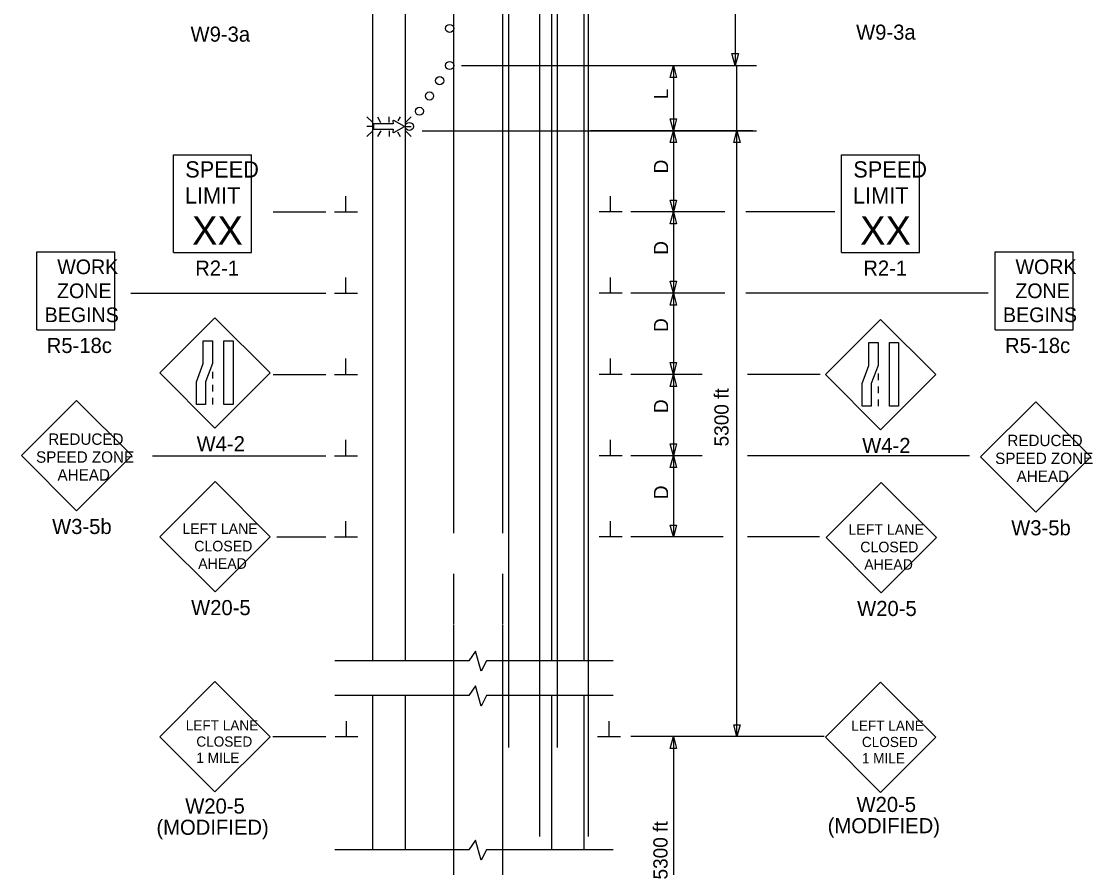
# Model space of a CAD drawing. Extents: x 16741 to 18482, y 7002 to 8333.
# Drawn here: x 16741 to 17268, y 7456 to 7872 of the extents above; entities that cross this region are included whole.
import ezdxf

# ---------------------------------------------------------------- set-up
doc = ezdxf.new("R2010")
doc.units = 0
for name, color, linetype in [('ALI_LEGAL_EX', 7, 'Continuous'), ('PAVT_EDGE_EX', 7, 'Continuous'), ('TRAFFIC_SIGNS_PR', 7, 'Continuous'), ('TYPICAL_TEXT_DIMEN_PR', 7, 'Continuous')]:
    doc.layers.add(name, color=color, linetype=linetype)

msp = doc.modelspace()

# ---------------------------------------------------------------- linework, layer by layer
at = {"layer": 'ALI_LEGAL_EX'}
for p, q in [((16980.68, 8333.08), (16980.68, 7514.94)), ((17004.68, 8333.08), (17004.68, 7514.94)), ((16995.95, 8289.26), (16995.95, 7471.12)), ((17019.95, 8289.26), (17019.95, 7471.12)), ((16953.87, 7620.35), (16953.87, 8241.48)), ((16977.87, 7620.35), (16977.87, 8241.48)), ((16953.87, 7497.94), (16953.87, 7575.09)), ((16977.87, 7497.94), (16977.87, 7575.09)), ((16953.87, 7379.99), (16953.87, 7560.8)), ((16977.87, 7379.99), (16977.87, 7560.8))]:
    msp.add_line(p, q, dxfattribs=at)
for points in [[(16953.87, 7775.35), (16953.87, 7800.35)], [(16977.87, 7775.35), (16977.87, 7800.35)], [(16953.87, 7675.35), (16953.87, 7700.35)], [(16977.87, 7675.35), (16977.87, 7700.35)], [(16953.87, 7575.35), (16953.87, 7600.35)], [(16977.87, 7575.35), (16977.87, 7600.35)], [(16953.87, 7475.35), (16953.87, 7500.35)], [(16977.87, 7475.35), (16977.87, 7500.35)]]:
    msp.add_lwpolyline(points, dxfattribs=at)
at = {"layer": 'PAVT_EDGE_EX'}
for p, q in [((16913.87, 8212.75), (16913.87, 7557.55)), ((16929.87, 8212.75), (16929.87, 7557.55)), ((17001.87, 8212.75), (17001.87, 7557.55)), ((17017.87, 8212.75), (17017.87, 7557.55)), ((16913.87, 7540.42), (16913.87, 7464.49)), ((16929.87, 7540.42), (16929.87, 7464.49)), ((17001.87, 7540.42), (17001.87, 7464.49)), ((17017.87, 7540.42), (17017.87, 7464.49))]:
    msp.add_line(p, q, dxfattribs=at)
at = {"layer": 'TRAFFIC_SIGNS_PR'}
for p, q in [((16913.89, 7822.57), (16911.06, 7825.39)), ((16916.18, 7825.39), (16917.81, 7822.57)), ((16921.97, 7822.57), (16921.97, 7825.39)), ((16927.44, 7825.39), (16926.23, 7823.3)), ((16932.87, 7825.39), (16930.06, 7822.57)), ((16913.89, 7820.54), (16911.06, 7820.54)), ((16930.06, 7820.54), (16932.87, 7820.54)), ((16913.89, 7818.5), (16911.06, 7815.68)), ((16917.83, 7818.5), (16916.21, 7815.68)), ((16921.97, 7818.5), (16921.97, 7815.68)), ((16926.15, 7817.87), (16927.41, 7815.68)), ((16932.87, 7815.69), (16930.06, 7818.5)), ((16815.84, 7806.57), (16854.24, 7806.57)), ((16815.84, 7758.57), (16815.84, 7806.57)), ((16854.24, 7758.57), (16854.24, 7806.57)), ((17144.69, 7806.57), (17183.09, 7806.57)), ((17144.69, 7758.57), (17144.69, 7806.57)), ((17183.09, 7758.57), (17183.09, 7806.57)), ((16748.63, 7720.5), (16748.63, 7758.9)), ((16748.63, 7758.9), (16787.03, 7758.9)), ((16787.03, 7720.5), (16787.03, 7758.9)), ((16815.84, 7758.57), (16854.24, 7758.57)), ((17144.69, 7758.57), (17183.09, 7758.57)), ((17220.32, 7720.5), (17220.32, 7758.9)), ((17220.32, 7758.9), (17258.72, 7758.9)), ((17258.72, 7720.5), (17258.72, 7758.9)), ((16836.26, 7726.42), (16809.1, 7699.26)), ((16863.41, 7699.26), (16836.26, 7726.42)), ((17163.88, 7725.58), (17136.72, 7698.43)), ((17191.03, 7698.43), (17163.88, 7725.58)), ((16748.63, 7720.5), (16787.03, 7720.5)), ((17220.32, 7720.5), (17258.72, 7720.5)), ((16809.1, 7699.26), (16836.26, 7672.11)), ((16835.01, 7699.75), (16835.01, 7696.55)), ((16836.26, 7672.11), (16863.41, 7699.26)), ((17136.72, 7698.43), (17163.88, 7671.27)), ((17162.63, 7698.92), (17162.63, 7695.72)), ((17163.88, 7671.27), (17191.03, 7698.43)), ((16835.01, 7693.35), (16835.01, 7690.15)), ((17162.63, 7692.52), (17162.63, 7689.32)), ((16768.14, 7685.7), (16740.98, 7658.54)), ((16795.29, 7658.54), (16768.14, 7685.7)), ((16835.01, 7686.95), (16835.01, 7683.75)), ((17162.63, 7686.12), (17162.63, 7682.92)), ((17240.23, 7685.06), (17213.08, 7657.9)), ((17267.38, 7657.9), (17240.23, 7685.06)), ((16740.98, 7658.54), (16768.14, 7631.39)), ((16768.14, 7631.39), (16795.29, 7658.54)), ((17213.08, 7657.9), (17240.23, 7630.75)), ((17240.23, 7630.75), (17267.38, 7657.9)), ((16836.33, 7645.76), (16809.18, 7618.6)), ((16863.48, 7618.6), (16836.33, 7645.76)), ((17164.17, 7645.32), (17137.02, 7618.17)), ((17191.33, 7618.17), (17164.17, 7645.32)), ((16809.18, 7618.6), (16836.33, 7591.45)), ((16836.33, 7591.45), (16863.48, 7618.6)), ((17137.02, 7618.17), (17164.17, 7591.01)), ((17164.17, 7591.01), (17191.33, 7618.17)), ((16836.25, 7547.29), (16809.1, 7520.14)), ((16863.4, 7520.14), (16836.25, 7547.29)), ((17163.85, 7547.08), (17136.7, 7519.92)), ((17191, 7519.92), (17163.85, 7547.08)), ((16809.1, 7520.14), (16836.25, 7492.98)), ((16836.25, 7492.98), (16863.4, 7520.14)), ((17136.7, 7519.92), (17163.85, 7492.77)), ((17163.85, 7492.77), (17191, 7519.92))]:
    msp.add_line(p, q, dxfattribs=at)
for points in [[(16923.8, 7823.22), (16924.03, 7821.92), (16914.3, 7821.92), (16914.3, 7819.18), (16924.03, 7819.18), (16923.8, 7817.88)], [(16924.3, 7817.52), (16929.61, 7820.54), (16924.3, 7823.58)]]:
    msp.add_lwpolyline(points, dxfattribs=at)
for points in [[(16835.01, 7715), (16835.01, 7703.82), (16831.66, 7694.94), (16831.66, 7683.75), (16827.17, 7683.75), (16827.17, 7694.94), (16830.51, 7703.82), (16830.51, 7715)], [(16845.14, 7715), (16845.14, 7683.75), (16840.65, 7683.75), (16840.65, 7715)], [(17162.63, 7714.16), (17162.63, 7702.98), (17159.29, 7694.1), (17159.29, 7682.92), (17154.79, 7682.92), (17154.79, 7694.1), (17158.14, 7702.98), (17158.14, 7714.16)], [(17172.77, 7714.16), (17172.77, 7682.92), (17168.27, 7682.92), (17168.27, 7714.16)]]:
    msp.add_lwpolyline(points, close=True, dxfattribs=at)
for centre in [(16951.8, 7868.82), (16951.8, 7850.6), (16946.83, 7843.09), (16941.87, 7835.59), (16936.9, 7828.08), (16931.93, 7820.58)]:
    msp.add_circle(centre, 2, dxfattribs=at)
for centre, start, end in [((16924.13, 7823.28), 61.4833, 189.9593), ((16924.13, 7817.82), 170.7308, 298.8916)]:
    msp.add_arc(centre, 0.341, start, end, dxfattribs=at)
at = {"layer": 'TYPICAL_TEXT_DIMEN_PR'}
for p, q in [((17092.3, 7968.48), (17092.3, 7850.6)), ((17092.3, 7850.6), (17090.73, 7856.46)), ((17090.73, 7856.46), (17092.3, 7856.46)), ((17092.3, 7856.46), (17093.87, 7856.46)), ((17093.87, 7856.46), (17092.3, 7850.6)), ((16957.62, 7850.6), (17066.87, 7850.6)), ((16957.62, 7850.6), (17102.73, 7850.6)), ((17060.3, 7844.74), (17061.87, 7850.6)), ((17061.87, 7850.6), (17061.87, 7818.5)), ((17061.87, 7850.6), (17063.44, 7844.74)), ((17093.18, 7520.21), (17093.18, 7850.6)), ((17061.87, 7844.74), (17060.3, 7844.74)), ((17063.44, 7844.74), (17061.87, 7844.74)), ((17061.87, 7818.5), (17060.3, 7824.36)), ((17060.3, 7824.36), (17061.87, 7824.36)), ((17061.87, 7824.36), (17063.44, 7824.36)), ((17063.44, 7824.36), (17061.87, 7818.5)), ((16938.26, 7818.5), (17102.73, 7818.5)), ((16957.62, 7818.5), (17066.87, 7818.5)), ((17100.98, 7818.5), (17021.17, 7818.5)), ((17060.3, 7812.64), (17061.87, 7818.5)), ((17061.87, 7818.5), (17061.87, 7778.5)), ((17061.87, 7818.5), (17063.44, 7812.64)), ((17091.62, 7812.64), (17093.19, 7818.5)), ((17093.19, 7818.5), (17094.76, 7812.64)), ((17061.87, 7812.64), (17060.3, 7812.64)), ((17063.44, 7812.64), (17061.87, 7812.64)), ((17093.19, 7812.64), (17091.62, 7812.64)), ((17094.76, 7812.64), (17093.19, 7812.64)), ((16900.74, 7778.5), (16900.74, 7786.28)), ((16900.74, 7778.5), (16900.74, 7786.28)), ((17030.99, 7778.5), (17030.99, 7786.28)), ((17061.87, 7778.5), (17060.3, 7784.36)), ((17060.3, 7784.36), (17061.87, 7784.36)), ((17061.87, 7784.36), (17063.44, 7784.36)), ((17063.44, 7784.36), (17061.87, 7778.5)), ((16864.87, 7778.5), (16890.87, 7778.5)), ((16866.23, 7778.5), (16890.87, 7778.5)), ((16895.12, 7778.5), (16906.37, 7778.5)), ((16895.12, 7778.5), (16906.37, 7778.5)), ((17036.62, 7778.5), (17025.37, 7778.5)), ((17087.19, 7778.5), (17040.87, 7778.5)), ((17060.3, 7772.64), (17061.87, 7778.5)), ((17061.87, 7778.5), (17061.87, 7738.5)), ((17061.87, 7778.5), (17063.44, 7772.64)), ((17141.44, 7778.5), (17097.48, 7778.5)), ((17061.87, 7772.64), (17060.3, 7772.64)), ((17063.44, 7772.64), (17061.87, 7772.64)), ((16900.74, 7738.5), (16900.74, 7746.28)), ((16900.74, 7738.5), (16900.74, 7746.28)), ((17030.99, 7738.5), (17030.99, 7746.28)), ((17061.87, 7738.5), (17060.3, 7744.36)), ((17060.3, 7744.36), (17061.87, 7744.36)), ((17061.87, 7744.36), (17063.44, 7744.36)), ((17063.44, 7744.36), (17061.87, 7738.5)), ((16794.8, 7738.5), (16890.87, 7738.5)), ((16864.87, 7738.5), (16890.87, 7738.5)), ((16895.12, 7738.5), (16906.37, 7738.5)), ((16895.12, 7738.5), (16906.37, 7738.5)), ((17036.62, 7738.5), (17025.37, 7738.5)), ((17087.19, 7738.5), (17040.87, 7738.5)), ((17060.3, 7732.64), (17061.87, 7738.5)), ((17061.87, 7738.5), (17061.87, 7698.5)), ((17061.87, 7738.5), (17063.44, 7732.64)), ((17216.84, 7738.5), (17097.48, 7738.5)), ((17061.87, 7732.64), (17060.3, 7732.64)), ((17063.44, 7732.64), (17061.87, 7732.64)), ((16900.74, 7698.5), (16900.74, 7706.28)), ((16900.74, 7698.5), (16900.74, 7706.28)), ((17030.99, 7698.5), (17030.99, 7706.28)), ((17061.87, 7698.5), (17060.3, 7704.36)), ((17060.3, 7704.36), (17061.87, 7704.36)), ((17061.87, 7704.36), (17063.44, 7704.36)), ((17063.44, 7704.36), (17061.87, 7698.5)), ((16864.87, 7698.5), (16890.87, 7698.5)), ((16878.29, 7698.5), (16890.87, 7698.5)), ((16895.12, 7698.5), (16906.37, 7698.5)), ((16895.12, 7698.5), (16906.37, 7698.5)), ((17036.62, 7698.5), (17025.37, 7698.5)), ((17076.06, 7698.5), (17040.87, 7698.5)), ((17060.3, 7692.64), (17061.87, 7698.5)), ((17061.87, 7698.5), (17063.44, 7692.64)), ((17061.87, 7698.5), (17061.87, 7658.5)), ((17134.13, 7698.5), (17098.32, 7698.5)), ((17061.87, 7692.64), (17060.3, 7692.64)), ((17063.44, 7692.64), (17061.87, 7692.64)), ((16900.74, 7658.5), (16900.74, 7666.28)), ((16900.74, 7658.5), (16900.74, 7666.28)), ((17030.99, 7658.5), (17030.99, 7666.28)), ((17061.87, 7658.5), (17060.3, 7664.36)), ((17060.3, 7664.36), (17061.87, 7664.36)), ((17061.87, 7664.36), (17063.44, 7664.36)), ((17063.44, 7664.36), (17061.87, 7658.5)), ((16805.43, 7658.5), (16890.87, 7658.5)), ((16864.87, 7658.5), (16890.87, 7658.5)), ((16895.12, 7658.5), (16906.37, 7658.5)), ((16895.12, 7658.5), (16906.37, 7658.5)), ((17036.62, 7658.5), (17025.37, 7658.5)), ((17076.06, 7658.5), (17040.87, 7658.5)), ((17060.3, 7652.64), (17061.87, 7658.5)), ((17061.87, 7658.5), (17061.87, 7618.5)), ((17061.87, 7658.5), (17063.44, 7652.64)), ((17207.59, 7658.5), (17098.32, 7658.5)), ((17061.87, 7652.64), (17060.3, 7652.64)), ((17063.44, 7652.64), (17061.87, 7652.64)), ((16900.74, 7618.5), (16900.74, 7626.28)), ((17030.99, 7618.5), (17030.99, 7626.28)), ((17061.87, 7618.5), (17060.3, 7624.36)), ((17060.3, 7624.36), (17061.87, 7624.36)), ((17061.87, 7624.36), (17063.44, 7624.36)), ((17063.44, 7624.36), (17061.87, 7618.5)), ((16866.72, 7618.5), (16890.87, 7618.5)), ((16895.12, 7618.5), (16906.37, 7618.5)), ((17036.62, 7618.5), (17025.37, 7618.5)), ((17086.35, 7618.5), (17040.87, 7618.5)), ((17133.74, 7618.5), (17098.32, 7618.5)), ((16964.47, 7562.35), (16961.21, 7557.55)), ((16967.21, 7552.41), (16964.47, 7562.35)), ((16961.21, 7557.55), (16895.27, 7557.55)), ((16969.95, 7557.55), (16967.21, 7552.41)), ((17032.29, 7557.55), (16969.95, 7557.55)), ((16964.47, 7545.22), (16961.21, 7540.42)), ((16967.21, 7535.28), (16964.47, 7545.22)), ((16961.21, 7540.42), (16895.27, 7540.42)), ((16969.95, 7540.42), (16967.21, 7535.28)), ((17032.29, 7540.42), (16969.95, 7540.42)), ((16900.96, 7520.11), (16900.96, 7527.89)), ((17030.24, 7520.11), (17030.24, 7527.89)), ((17093.19, 7520.21), (17091.62, 7526.07)), ((17091.62, 7526.07), (17093.19, 7526.07)), ((17093.19, 7526.07), (17094.76, 7526.07)), ((17094.76, 7526.07), (17093.19, 7520.21)), ((16864.72, 7520.21), (16890.87, 7520.21)), ((16906.59, 7520.11), (16895.34, 7520.11)), ((17035.87, 7520.11), (17024.62, 7520.11)), ((17136.16, 7520.21), (17040.87, 7520.21)), ((17060.3, 7514.35), (17061.87, 7520.21)), ((17061.87, 7520.21), (17061.87, 7416.94)), ((17061.87, 7520.21), (17063.44, 7514.35)), ((17061.87, 7514.35), (17060.3, 7514.35)), ((17063.44, 7514.35), (17061.87, 7514.35)), ((16964.47, 7469.29), (16961.21, 7464.49)), ((16967.21, 7459.35), (16964.47, 7469.29)), ((16961.21, 7464.49), (16895.27, 7464.49)), ((16969.95, 7464.49), (16967.21, 7459.35)), ((17032.29, 7464.49), (16969.95, 7464.49))]:
    msp.add_line(p, q, dxfattribs=at)

# ---------------------------------------------------------------- texts
at = {"layer": 'TRAFFIC_SIGNS_PR'}
for s, height, p in [('W9-3a', 7.44, (16824.23, 7862.3)), ('W9-3a', 7.44, (17151.83, 7863.27)), ('SPEED', 8, (16821.61, 7795.44)), ('SPEED', 8, (17150.46, 7795.44)), ('LIMIT', 8, (16821.45, 7782.64)), ('LIMIT', 8, (17150.3, 7782.64)), ('XX', 14.031, (16824.96, 7762.33)), ('XX', 14.031, (17153.8, 7762.33)), ('WORK', 7.217, (16758.63, 7747.87)), ('R2-1', 7.44, (16826.52, 7747.13)), ('R2-1', 7.44, (17155.37, 7747.13)), ('WORK', 7.217, (17230.32, 7747.87)), ('ZONE', 7.217, (16758.51, 7736.06)), ('ZONE', 7.217, (17230.2, 7736.06)), ('BEGINS', 7.217, (16752.44, 7724.25)), ('BEGINS', 7.217, (17224.13, 7724.25)), ('R5-18c', 7.44, (16753.44, 7709.06)), ('R5-18c', 7.44, (17225.13, 7709.06)), ('REDUCED', 5.6, (16754.19, 7663.85)), ('W4-2', 7.44, (16827.21, 7660.67)), ('W4-2', 7.44, (17154.84, 7659.83)), ('REDUCED', 5.6, (17226.29, 7663.21)), ('SPEED ZONE', 5.6, (16748.19, 7655.05)), ('SPEED ZONE', 5.6, (17220.28, 7654.41)), ('AHEAD', 5.6, (16758.75, 7646.25)), ('AHEAD', 5.6, (17230.84, 7645.61)), ('W3-5b', 7.44, (16756.09, 7619.95)), ('LEFT LANE', 5.2, (16820.21, 7620)), ('LEFT LANE', 5.2, (17148.06, 7619.56)), ('W3-5b', 7.44, (17228.18, 7619.31)), ('CLOSED', 5.2, (16826.04, 7611.4)), ('CLOSED', 5.2, (17153.89, 7610.96)), ('AHEAD', 5.2, (16827.99, 7602.8)), ('AHEAD', 5.2, (17155.83, 7602.36)), ('W20-5', 7.44, (16824.51, 7580.01)), ('W20-5', 7.44, (17152.35, 7579.58)), ('LEFT LANE', 5, (16821.88, 7523.29)), ('LEFT LANE', 5, (17149.48, 7523.08)), ('CLOSED', 5, (16827.09, 7515.29)), ('CLOSED', 5, (17154.69, 7515.08)), ('1 MILE', 5, (16827.08, 7507.3)), ('1 MILE', 5, (17154.68, 7507.08)), ('W20-5', 7.44, (16821.62, 7482.32)), ('W20-5', 7.44, (17152.03, 7483.11)), ('(MODIFIED)', 7.44, (16807.44, 7471.88)), ('(MODIFIED)', 7.44, (17137.85, 7472.67))]:
    msp.add_text(s, height=height, dxfattribs=at).set_placement(p)
at = {"layer": 'TYPICAL_TEXT_DIMEN_PR'}
for s, p in [('L', (17059.31, 7833.91)), ('D', (17059.31, 7797.46)), ('D', (17059.31, 7757.4)), ('D', (17059.31, 7719.42)), ('5300 ft', (17089.06, 7663.07)), ('D', (17059.31, 7679.47)), ('D', (17059.31, 7637.09)), ('5300 ft', (17059.02, 7449.89))]:
    msp.add_text(s, height=7, rotation=90, dxfattribs=at).set_placement(p)

doc.saveas('drawing.dxf')
